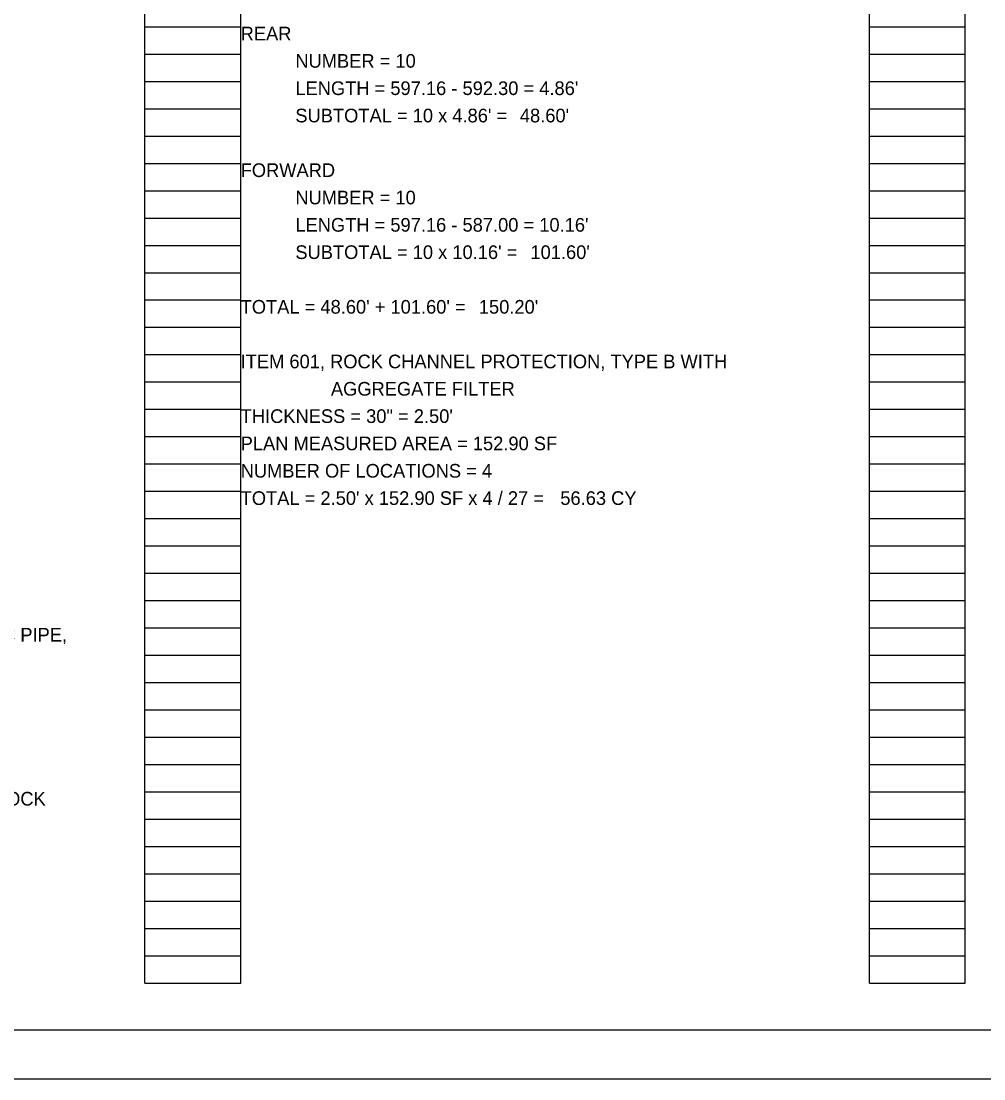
# Model space of a CAD drawing. Extents: x 0 to 34, y 0 to 22.
# Drawn here: x 14.99 to 24.85, y 0 to 10.84 of the extents above; entities that cross this region are included whole.
import ezdxf

# ---------------------------------------------------------------- set-up
doc = ezdxf.new("R2010")
doc.units = 0
for name, color, linetype in [('BR_P_Gen_Text', 7, 'Continuous'), ('SC_Scratch2', 7, 'Continuous'), ('SH_Border', 7, 'Continuous'), ('SH_Cut_Line', 7, 'Continuous')]:
    doc.layers.add(name, color=color, linetype=linetype)

msp = doc.modelspace()

# ---------------------------------------------------------------- linework, layer by layer
at = {"layer": 'SC_Scratch2'}
for p, q in [((16.26, 0.98), (16.26, 21.14)), ((17.24, 0.98), (17.24, 21.14)), ((23.68, 0.98), (23.68, 21.14)), ((24.66, 0.98), (24.66, 21.14)), ((16.26, 10.78), (17.24, 10.78)), ((23.68, 10.78), (24.66, 10.78)), ((16.26, 10.5), (17.24, 10.5)), ((23.68, 10.5), (24.66, 10.5)), ((16.26, 10.22), (17.24, 10.22)), ((23.68, 10.22), (24.66, 10.22)), ((16.26, 9.94), (17.24, 9.94)), ((23.68, 9.94), (24.66, 9.94)), ((16.26, 9.66), (17.24, 9.66)), ((23.68, 9.66), (24.66, 9.66)), ((16.26, 9.38), (17.24, 9.38)), ((23.68, 9.38), (24.66, 9.38)), ((16.26, 9.1), (17.24, 9.1)), ((23.68, 9.1), (24.66, 9.1)), ((16.26, 8.82), (17.24, 8.82)), ((23.68, 8.82), (24.66, 8.82)), ((16.26, 8.54), (17.24, 8.54)), ((23.68, 8.54), (24.66, 8.54)), ((16.26, 8.26), (17.24, 8.26)), ((23.68, 8.26), (24.66, 8.26)), ((16.26, 7.98), (17.24, 7.98)), ((23.68, 7.98), (24.66, 7.98)), ((16.26, 7.7), (17.24, 7.7)), ((23.68, 7.7), (24.66, 7.7)), ((16.26, 7.42), (17.24, 7.42)), ((23.68, 7.42), (24.66, 7.42)), ((16.26, 7.14), (17.24, 7.14)), ((23.68, 7.14), (24.66, 7.14)), ((16.26, 6.86), (17.24, 6.86)), ((23.68, 6.86), (24.66, 6.86)), ((16.26, 6.58), (17.24, 6.58)), ((23.68, 6.58), (24.66, 6.58)), ((16.26, 6.3), (17.24, 6.3)), ((23.68, 6.3), (24.66, 6.3)), ((16.26, 6.02), (17.24, 6.02)), ((23.68, 6.02), (24.66, 6.02)), ((16.26, 5.74), (17.24, 5.74)), ((23.68, 5.74), (24.66, 5.74)), ((16.26, 5.46), (17.24, 5.46)), ((23.68, 5.46), (24.66, 5.46)), ((16.26, 5.18), (17.24, 5.18)), ((23.68, 5.18), (24.66, 5.18)), ((16.26, 4.9), (17.24, 4.9)), ((23.68, 4.9), (24.66, 4.9)), ((16.26, 4.62), (17.24, 4.62)), ((23.68, 4.62), (24.66, 4.62)), ((16.26, 4.34), (17.24, 4.34)), ((23.68, 4.34), (24.66, 4.34)), ((16.26, 4.06), (17.24, 4.06)), ((23.68, 4.06), (24.66, 4.06)), ((16.26, 3.78), (17.24, 3.78)), ((23.68, 3.78), (24.66, 3.78)), ((16.26, 3.5), (17.24, 3.5)), ((23.68, 3.5), (24.66, 3.5)), ((16.26, 3.22), (17.24, 3.22)), ((23.68, 3.22), (24.66, 3.22)), ((16.26, 2.94), (17.24, 2.94)), ((23.68, 2.94), (24.66, 2.94)), ((16.26, 2.66), (17.24, 2.66)), ((23.68, 2.66), (24.66, 2.66)), ((16.26, 2.38), (17.24, 2.38)), ((23.68, 2.38), (24.66, 2.38)), ((16.26, 2.1), (17.24, 2.1)), ((23.68, 2.1), (24.66, 2.1)), ((16.26, 1.82), (17.24, 1.82)), ((23.68, 1.82), (24.66, 1.82)), ((16.26, 1.54), (17.24, 1.54)), ((23.68, 1.54), (24.66, 1.54)), ((16.26, 1.26), (17.24, 1.26)), ((23.68, 1.26), (24.66, 1.26)), ((16.26, 0.98), (17.24, 0.98)), ((23.68, 0.98), (24.66, 0.98))]:
    msp.add_line(p, q, dxfattribs=at)
at = {"layer": 'SH_Border'}
msp.add_lwpolyline([(1.5, 21.5), (33.5, 21.5), (33.5, 0.5), (1.5, 0.5)], close=True, dxfattribs=at)
at = {"layer": 'SH_Cut_Line'}
msp.add_lwpolyline([(0, 0), (34, 0), (34, 22), (0, 22)], close=True, dxfattribs=at)

# ---------------------------------------------------------------- texts
at = {"layer": 'BR_P_Gen_Text'}
for s, p in [('REAR', (17.24, 10.64)), ('NUMBER = 10', (17.8, 10.36)), ("LENGTH = 597.16 - 592.30 = 4.86'", (17.8, 10.08)), ("SUBTOTAL = 10 x 4.86' = ", (17.8, 9.8)), ("48.60'", (20.099, 9.8)), ('FORWARD', (17.24, 9.24)), ('NUMBER = 10', (17.8, 8.96)), ("LENGTH = 597.16 - 587.00 = 10.16'", (17.8, 8.68)), ("SUBTOTAL = 10 x 10.16' = ", (17.8, 8.4)), ("101.60'", (20.207, 8.4)), ("TOTAL = 48.60' + 101.60' = ", (17.24, 7.84)), ("150.20'", (19.679, 7.84)), ('ITEM 601, ROCK CHANNEL PROTECTION, TYPE B WITH ', (17.24, 7.28)), ('       AGGREGATE FILTER', (17.8, 7)), ('THICKNESS = 30" = 2.50\'', (17.24, 6.72)), ('PLAN MEASURED AREA = 152.90 SF', (17.24, 6.44)), ('NUMBER OF LOCATIONS = 4', (17.24, 6.16)), ("TOTAL = 2.50' x 152.90 SF x 4 / 27 = ", (17.24, 5.88)), ('56.63 CY', (20.513, 5.88)), ('ITEM 518, 6" NON-PERFORATED CORRUGATED PLASTIC PIPE, ', (9.82, 4.48)), ('ITEM 524, DRILLED SHAFTS, 30" DIAMETER, INTO BEDROCK', (9.82, 2.8))]:
    msp.add_text(s, height=0.14, dxfattribs=at).set_placement(p)

doc.saveas('drawing.dxf')
